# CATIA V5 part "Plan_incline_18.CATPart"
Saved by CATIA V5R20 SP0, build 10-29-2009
Part number: Plan_incline_18
Bounding box of the stored display mesh (mm): x -50 to 3, y -104.995 to 104.995, z -104.998 to 104.998
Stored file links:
  C:\Users\Thinkmotion2\Desktop\Pack 2\CFAO_2010\abaussand\CFAO_abaussand_Catia_V5R20\Plan_incline_18.CATPart
  C:\Users\Alex\IFMA\2A\CFAO\pompe\pompe.CATProduct
  C:\Users\Thinkmotion2\Desktop\Pack 2\CFAO_2010\abaussand\CFAO_abaussand_Catia_V5R20\corps_12.CATPart
  C:\Users\Thinkmotion2\Desktop\Pack 2\CFAO_2010\abaussand\CFAO_abaussand_Catia_V5R20\abaussand_2.CATProduct
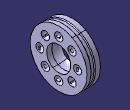
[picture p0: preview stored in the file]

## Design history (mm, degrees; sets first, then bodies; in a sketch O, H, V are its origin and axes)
External parameters (linked from other documents)
  `External.Diamètre_piston_16` = 30 mm
  External.Positionnement_piston = 60 mm
  External.Nombre_pistons = 8
  External.Positionnement_piston.1 = 70 mm
Body1 (main body)
  Sketch1 on zx-plane, origin (0, 0, 0), H (-1, 0, 0), V (0, 0, 1)
    line L1 (19.7157, 45) -> (0, 45)
    point P4 (0, 45)
    line L2 (50, 105) -> (32, 105)
    line L3 (32, 105) -> (29, 102)
    line L4 (29, 102) -> (18, 102)
    line L5 (18, 102) -> (15, 105)
    line L6 (15, 105) -> (0, 105)
    point P9 (0, 45)
    line L7 (0, 45) -> (0, 105)
    line L8 (50, 105) -> (50, 60)
    line L9 (50, 60) -> (48, 60)
    line L10 (48, 60) -> (48, 35)
    arc A1 centre (19.7157, 0) radius 45 from (48, 35) to (19.7157, 45) ccw
    distance H L1 = 45
    length L2 = 18
    distance L4 L2 = 3
    angle L3 L4 = 45
    angle L5 L4 = 45
    length L6 = 15
    distance L2 L1 = 60
    length L9 = 2
    distance L9 L1 = 15
    length L10 = 25
    radius A1 = 45
    distance L8 L7 = 50
    horizontal: L1 H, L2 H, L4 H, L6 H, L9 H
    vertical: L7 V, L8 V, L10 V
    coincidence: L2 L6, P9 P4, L7 V
    tangency: A1 L1
  Shaft1: profile Sketch1, axis Sketch1.H, angle 360
  Point1: type Center, Curve edge [face of Shaft1 from Sketch1.L8 | face of Shaft1 from Sketch1.L9]
  Plane1: type OffsetPt, RefPlane yz-plane, RefPoint Point1
  Sketch2 on Plane1, origin (-50, 0, 0), H (0, 1, 0), V (0, 0, 1)
    arc A1 centre (0, 0) radius 90 from (15.5161, 88.6524) to (-14.3535, 88.8481) ccw
    point P1 (0, 90)
    arc A2 centre (0, 0) radius 75 from (12.9301, 73.877) to (-11.9612, 74.0401) ccw
    point P2 (0, 75)
    arc A3 centre (14.2231, 81.2647) radius 7.5 from (15.5161, 88.6524) to (12.9301, 73.877) cw
    arc A4 centre (-13.1573, 81.4441) radius 7.5 from (-14.3535, 88.8481) to (-11.9612, 74.0401) ccw
    radius A1 = 90
    radius A2 = 75
    coincidence: A1 P1, P1 V, A2 P2, P2 V
    tangency: A3 A1, A3 A2, A4 A1, A4 A2
  Pocket1: profile Sketch2, direction (1, 0, 0), length 2
  CircPattern1: of Pocket1, instances 8, angular step 45, axis from face of Shaft1 from Sketch1.L2
  Point2: type OnPlane, Support xy-plane, H -19.716, V 0, Direction (1, 0, 0)
  Sketch3 on face of Shaft1 from Sketch1.L7, origin (0, 0, 0), H (0, 1, 0), V (0, 0, 1)
    line L1 (0, 85) -> (0, 55)
    point P1 (0, 85)
    arc A1 centre (0, 70) radius 15 from (0, 85) to (0, 55) cw
    point P3 (0, 70)
    radius A1 = 15
    distance P3 L1 = 0
    distance P3 H = 70
    coincidence: P1 V
    vertical: L1 V
  Groove1: profile Sketch3, axis Sketch3.L1, angle 180
  CircPattern2: of Groove1, instances 8, angular step 45, axis from face of Shaft1 from Sketch1.L1
  Point3: type Center, Curve edge [face of Shaft1 from Sketch1.L7 | face of Groove1 from Sketch3.A1]
  Point4: type Center, Curve edge [face of Shaft1 from Sketch1.L7 | face of CircPattern2]
  Point5: type Center, Curve edge [face of CircPattern2 | face of Shaft1 from Sketch1.L7]
  Point6: type Center, Curve edge [face of CircPattern2 | face of Shaft1 from Sketch1.L7]
  Point7: type Center, Curve edge [face of CircPattern2 | face of Shaft1 from Sketch1.L7]
  Point8: type Center, Curve edge [face of CircPattern2 | face of Shaft1 from Sketch1.L7]
  Point9: type Center, Curve edge [face of CircPattern2 | face of Shaft1 from Sketch1.L7]
  Point10: type Center, Curve edge [face of CircPattern2 | face of Shaft1 from Sketch1.L7]
  Point11: type Center, Curve face of Groove1 from Sketch3.A1
  Point12: type Center, Curve face of CircPattern2
  Point13: type Center, Curve face of CircPattern2
  Point14: type Center, Curve face of CircPattern2
  Point15: type Center, Curve face of CircPattern2
  Point16: type Center, Curve face of CircPattern2
  Point17: type Center, Curve face of CircPattern2
  Point18: type Center, Curve face of CircPattern2
  Line1: type PtDir, RefPoint Point12, Direction face of Shaft1 from Sketch1.L7, Start 0, End 100
  Line2: type PtDir, RefPoint Point11, Direction face of Shaft1 from Sketch1.L7, Start 0, End 100
  Line3: type PtDir, RefPoint Point18, Direction face of Shaft1 from Sketch1.L7, Start 0, End 100
  Line4: type PtDir, RefPoint Point17, Direction face of Shaft1 from Sketch1.L7, Start 0, End 100
  Line5: type PtDir, RefPoint Point16, Direction face of Shaft1 from Sketch1.L7, Start 0, End 100
  Line6: type PtDir, RefPoint Point15, Direction face of Shaft1 from Sketch1.L7, Start 0, End 100
  Line7: type PtDir, RefPoint Point14, Direction face of Shaft1 from Sketch1.L7, Start 0, End 100
  Line8: type PtDir, RefPoint Point13, Direction face of Shaft1 from Sketch1.L7, Start 0, End 100
  Point19: type Center, Curve edge [face of Shaft1 from Sketch1.L1 | face of Shaft1 from Sketch1.L7]
  Line9: type PtDir, RefPoint Point19, Direction face of Shaft1 from Sketch1.L7, Start 0, End 100
  Plane2: type 1Line1Pt, RefPoint Point14, Line Line9
  Plane3: type 1Line1Pt, RefPoint Point13, Line Line9
  Plane4: type 1Line1Pt, RefPoint Point12, Line Line9
  Plane5: type 1Line1Pt, RefPoint Point11, Line Line9
  Plane6: type 1Line1Pt, RefPoint Point18, Line Line9
  Plane7: type 1Line1Pt, RefPoint Point17, Line Line9
  Plane8: type 1Line1Pt, RefPoint Point16, Line Line9
  Plane9: type 1Line1Pt, RefPoint Point15, Line Line9
  Line10: type PtDir, RefPoint Point13, Direction Plane3, Start -20, End 20
  Line11: type PtDir, RefPoint Point12, Direction Plane4, Start -20, End 20
  Line12: type PtDir, RefPoint Point11, Direction Plane5, Start -20, End 20
  Line13: type PtDir, RefPoint Point18, Direction Plane6, Start -20, End 20
  Line14: type PtDir, RefPoint Point17, Direction Plane7, Start -20, End 20
  Line15: type PtDir, RefPoint Point16, Direction Plane8, Start -20, End 20
  Line16: type PtDir, RefPoint Point15, Direction Plane9, Start -20, End 20
  Line17: type PtDir, RefPoint Point14, Direction Plane2, Start -20, End 20
  Sketch4 on Plane2, origin (0, 0, 0), H (1, 0, 0), V (0, 0.7071, 0.7071)
    circle A1 centre (0, -70) radius 3
    point P1 (0, -70)
    reference projected point E1 (0, -70) from edge
    radius A1 = 3
    coincidence: P1 E1
  Pad1: profile Sketch4, direction (0, -0.7071, 0.7071), length 5, opposite side length 5
  CircPattern3: of Pad1, instances 8, angular step 45, axis from face of Shaft1 from Sketch1.L7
